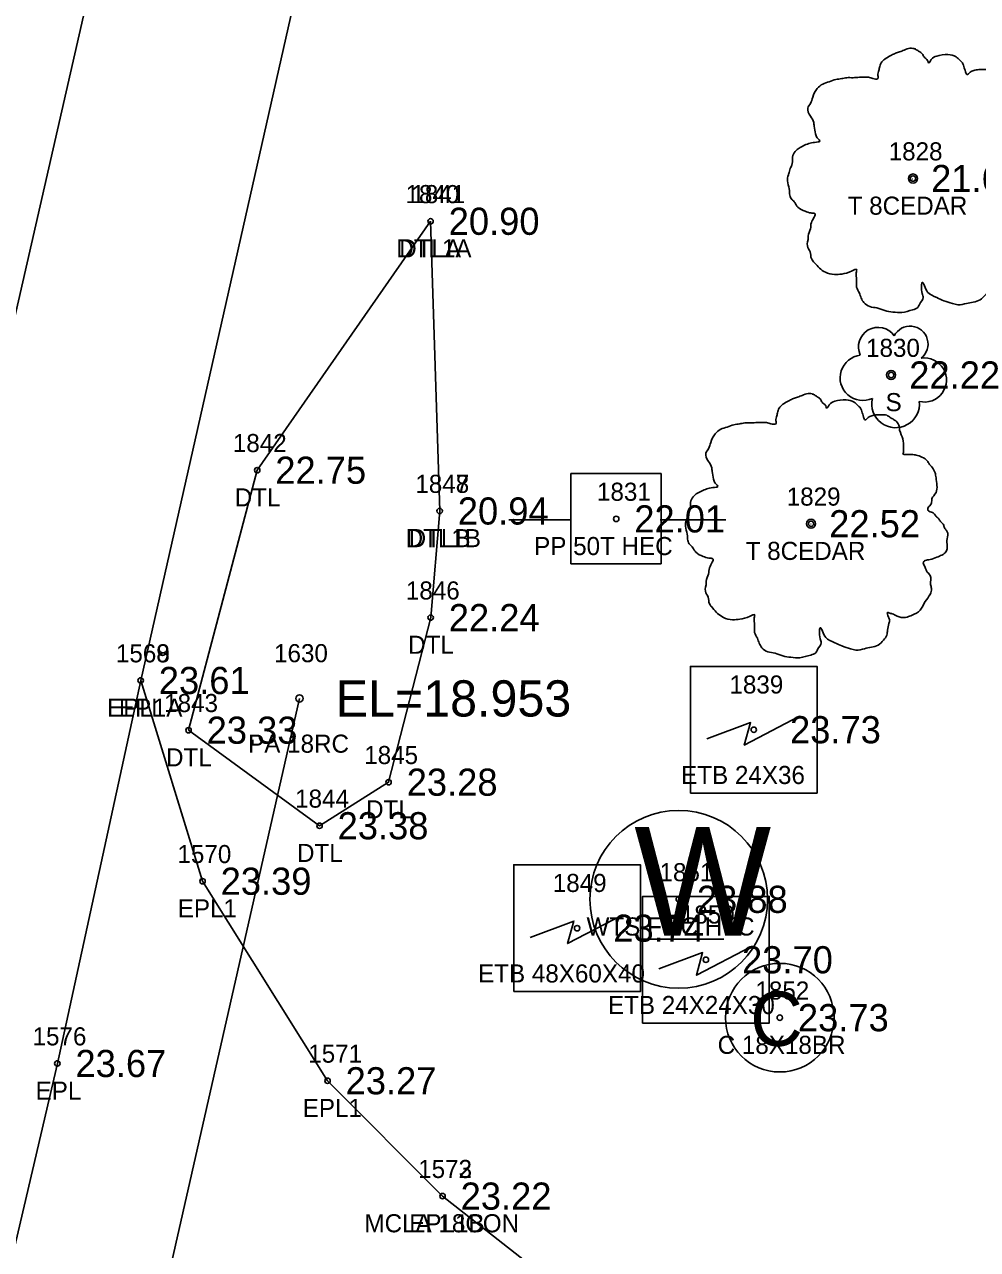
# Model space of a CAD drawing. Extents: x 2654414 to 2656963, y 761776 to 764965.
# Drawn here: x 2655624.8 to 2655677.5, y 762792.6 to 762860.3 of the extents above; entities that cross this region are included whole.
import ezdxf

# ---------------------------------------------------------------- set-up
doc = ezdxf.new("R2010")
doc.units = 0
for name, color, linetype in [('Default', 7, 'Continuous'), ('RD_EX_BldgApp', 7, 'Continuous'), ('RD_EX_BldgApp_txCode', 7, 'Continuous'), ('RD_EX_Conc', 7, 'Continuous'), ('RD_EX_Conc_txCode', 7, 'Continuous'), ('RD_EX_DR_Pipe', 7, 'Continuous'), ('RD_EX_DR_Pipe_txCode', 7, 'Continuous'), ('RD_EX_H2O', 7, 'Continuous'), ('RD_EX_H2O_txCode', 7, 'Continuous'), ('RD_EX_Road', 7, 'Continuous'), ('RD_EX_Road_txCode', 7, 'Continuous'), ('RD_EX_TX_BldgApp_ELEV', 7, 'Continuous'), ('RD_EX_TX_Conc_ELEV', 7, 'Continuous'), ('RD_EX_TX_H2O_ELEV', 7, 'Continuous'), ('RD_EX_TX_Road_ELEV', 7, 'Continuous'), ('RD_EX_TX_UT_ELEV', 7, 'Continuous'), ('RD_EX_TX_VEG_ELEV', 7, 'Continuous'), ('RD_EX_UT', 7, 'Continuous'), ('RD_EX_UT_txCode', 7, 'Continuous'), ('RD_EX_VEG', 7, 'Continuous'), ('RD_EX_VEG_txCode', 7, 'Continuous'), ('RD_HC_Cl', 7, 'Continuous'), ('RD_HC_Survey_ELEV', 7, 'Continuous'), ('RD_SMD_Locator', 7, 'Continuous'), ('RD_TX_Pipe_ElevEX', 7, 'Continuous')]:
    doc.layers.add(name, color=color, linetype=linetype)

msp = doc.modelspace()

# ---------------------------------------------------------------- linework, layer by layer
at = {"layer": 'Default'}
msp.add_line((2656050.51, 764712.367), (2655383.263, 761787.511), dxfattribs=at)
at = {"layer": 'RD_EX_BldgApp'}
msp.add_circle((2655666.585, 762805.403), 3, dxfattribs=at)
at = {"layer": 'RD_EX_Conc'}
msp.add_lwpolyline([(2655647.949, 762795.546), (2655656.497, 762788.848), (2655668.299, 762784.324), (2655695.432, 762778.051), (2655712.437, 762774.144), (2655737.025, 762767.62), (2655754.836, 762760.944), (2655757.409, 762759.817), (2655785.931, 762744.562)], dxfattribs=at)
at = {"layer": 'RD_EX_DR_Pipe'}
msp.add_line((2655640.047, 762823.04), (2655619.306, 762731.781), dxfattribs=at)
at = {"layer": 'RD_EX_H2O'}
msp.add_line((2655647.288, 762849.401), (2655647.792, 762833.395), dxfattribs=at)
msp.add_lwpolyline([(2655647.288, 762849.401), (2655637.708, 762835.648), (2655633.913, 762821.285), (2655641.15, 762816.006), (2655644.968, 762818.413), (2655647.293, 762827.505), (2655647.792, 762833.395)], dxfattribs=at)
at = {"layer": 'RD_EX_Road'}
for points in [[(2655670.037, 762995.178), (2655648.569, 762900.673), (2655631.27, 762824.032), (2655626.665, 762802.872), (2655621.781, 762781.907), (2655611.705, 762738.435), (2655604.931, 762708.622), (2655582.644, 762610.543), (2655576.456, 762583.319), (2655561.406, 762517.242), (2655539.154, 762414.805), (2655531.984, 762386.147), (2655517.984, 762324.295), (2655508.173, 762280.146), (2655501.462, 762251.601), (2655496.922, 762232.086), (2655477.204, 762144.974), (2655472.137, 762122.524), (2655453.741, 762045.099), (2655431.791, 761949.924), (2655409.76, 761853.25), (2655401.248, 761816.416), (2655394.612, 761787.366)], [(2655631.27, 762824.032), (2655634.687, 762812.942), (2655641.592, 762801.917), (2655647.949, 762795.546)]]:
    msp.add_lwpolyline(points, dxfattribs=at)
at = {"layer": 'RD_EX_UT'}
for p, q in [((2655660.036, 762835.467), (2655655.036, 762835.467)), ((2655655.036, 762835.467), (2655655.036, 762830.467)), ((2655660.036, 762830.467), (2655660.036, 762835.467)), ((2655651.605, 762832.905), (2655655.074, 762832.905)), ((2655659.965, 762832.905), (2655663.605, 762832.905)), ((2655655.036, 762830.467), (2655660.036, 762830.467)), ((2655658.872, 762809.734), (2655663.501, 762809.734))]:
    msp.add_line(p, q, dxfattribs=at)
for points in [[(2655661.649, 762817.811), (2655661.649, 762824.811), (2655668.649, 762824.811), (2655668.649, 762817.811)], [(2655651.886, 762806.847), (2655651.886, 762813.847), (2655658.886, 762813.847), (2655658.886, 762806.847)], [(2655658.999, 762805.103), (2655658.999, 762812.103), (2655665.999, 762812.103), (2655665.999, 762805.103)]]:
    msp.add_lwpolyline(points, close=True, dxfattribs=at)
for points in [[(2655662.547, 762820.805), (2655664.969, 762821.705), (2655664.623, 762820.459), (2655667.668, 762822.052)], [(2655652.784, 762809.841), (2655655.207, 762810.741), (2655654.861, 762809.495), (2655657.906, 762811.088)], [(2655659.898, 762808.097), (2655662.32, 762808.998), (2655661.974, 762807.751), (2655665.019, 762809.344)]]:
    msp.add_lwpolyline(points, dxfattribs=at)
msp.add_circle((2655661, 762811.942), 4.908, dxfattribs=at)
at = {"layer": 'RD_EX_VEG'}
for centre, radius in [((2655673.947, 762851.763), 0.25), ((2655673.934, 762851.744), 0.0001), ((2655672.737, 762840.909), 0.25), ((2655668.312, 762832.691), 0.25), ((2655668.3, 762832.672), 0.0001)]:
    msp.add_circle(centre, radius, dxfattribs=at)
for centre, radius, start, end in [((2655672.016, 762842.457), 1.084, 34.97629, 204.75602), ((2655673.782, 762842.611), 0.995, 308.76261, 152.04674), ((2655671.173, 762840.754), 1.257, 96.45179, 294.73401), ((2655674.577, 762840.63), 1.218, 256.56668, 98.10463), ((2655672.983, 762839.313), 1.318, 166.88266, 5.75893)]:
    msp.add_arc(centre, radius, start, end, dxfattribs=at)
for points in [[(2655674.079, 762858.93), (2655673.779, 762858.955), (2655673.454, 762858.855), (2655673.204, 762858.755), (2655672.979, 762858.68), (2655672.755, 762858.58), (2655672.455, 762858.406), (2655672.23, 762858.206), (2655672.105, 762857.956), (2655672.055, 762857.731), (2655672.005, 762857.456), (2655672.005, 762857.281), (2655671.88, 762857.256), (2655671.73, 762857.281), (2655671.48, 762857.356), (2655671.23, 762857.356), (2655670.98, 762857.356), (2655670.63, 762857.331), (2655670.281, 762857.331), (2655670.006, 762857.281), (2655669.681, 762857.231), (2655669.306, 762857.106), (2655668.956, 762856.981), (2655668.656, 762856.731), (2655668.406, 762856.256), (2655668.281, 762855.907), (2655668.132, 762855.657), (2655668.281, 762855.207), (2655668.456, 762854.857), (2655668.481, 762854.657), (2655668.556, 762854.232), (2655668.656, 762854.007), (2655668.781, 762853.807), (2655668.706, 762853.783), (2655668.331, 762853.733), (2655668.032, 762853.633), (2655667.607, 762853.408), (2655667.382, 762853.183), (2655667.282, 762852.858), (2655667.257, 762852.508), (2655667.157, 762852.308), (2655667.082, 762852.033), (2655667.057, 762851.958), (2655667.007, 762851.633), (2655667.107, 762851.184), (2655667.132, 762850.834), (2655667.257, 762850.609), (2655667.407, 762850.434), (2655667.582, 762850.184), (2655667.982, 762849.959), (2655668.306, 762849.859), (2655668.506, 762849.834), (2655668.331, 762849.334), (2655668.281, 762848.985), (2655668.157, 762848.585), (2655668.157, 762848.51), (2655668.107, 762848.035), (2655668.256, 762847.71), (2655668.331, 762847.335), (2655668.506, 762847.11), (2655668.781, 762846.811), (2655669.106, 762846.586), (2655669.606, 762846.461), (2655670.006, 762846.486), (2655670.581, 762846.661), (2655670.83, 762846.736), (2655670.805, 762846.561), (2655670.83, 762846.186), (2655670.83, 762845.761), (2655670.98, 762845.436), (2655671.08, 762845.161), (2655671.23, 762844.911), (2655671.555, 762844.687), (2655671.955, 762844.612), (2655672.38, 762844.462), (2655672.83, 762844.387), (2655673.329, 762844.362), (2655673.929, 762844.512), (2655674.204, 762844.637), (2655674.304, 762844.811), (2655674.504, 762845.186), (2655674.454, 762845.411), (2655674.479, 762846.011), (2655674.579, 762845.836), (2655674.754, 762845.486), (2655675.253, 762845.186), (2655675.653, 762845.011), (2655676.128, 762844.861), (2655676.428, 762844.786), (2655676.903, 762844.861), (2655677.278, 762844.936), (2655677.652, 762845.061), (2655677.952, 762845.336), (2655678.127, 762845.611), (2655678.177, 762845.886), (2655678.252, 762846.261), (2655678.302, 762846.436)], [(2655678.302, 762846.436), (2655678.227, 762846.611), (2655678.177, 762846.861), (2655678.252, 762846.836), (2655678.427, 762846.786), (2655678.702, 762846.661), (2655678.927, 762846.586), (2655679.252, 762846.611), (2655679.527, 762846.711), (2655679.976, 762846.986), (2655680.251, 762847.46), (2655680.526, 762847.86), (2655680.601, 762848.185), (2655680.551, 762848.41), (2655680.526, 762848.91), (2655680.326, 762849.16), (2655680.276, 762849.284), (2655680.176, 762849.684), (2655680.251, 762849.734), (2655680.526, 762849.784), (2655680.901, 762849.909), (2655681.176, 762850.034), (2655681.401, 762850.209), (2655681.476, 762850.434), (2655681.451, 762850.834), (2655681.501, 762851.234), (2655681.426, 762851.384), (2655681.326, 762851.533), (2655681.251, 762851.733), (2655681.101, 762851.883), (2655681.001, 762852.033), (2655680.901, 762852.133), (2655680.776, 762852.283), (2655680.601, 762852.408), (2655680.451, 762852.458), (2655680.401, 762852.608), (2655680.551, 762852.808), (2655680.601, 762852.908), (2655680.626, 762853.133), (2655680.851, 762853.483), (2655680.901, 762853.882), (2655680.851, 762854.307), (2655680.801, 762854.582), (2655680.651, 762854.857), (2655680.451, 762855.107), (2655680.326, 762855.282), (2655680.151, 762855.407), (2655679.826, 762855.532), (2655679.577, 762855.582), (2655679.227, 762855.582), (2655679.027, 762855.632), (2655679.052, 762855.682), (2655679.052, 762855.832), (2655679.052, 762856.107), (2655678.977, 762856.556), (2655678.827, 762857.056), (2655678.827, 762857.081), (2655678.727, 762857.331), (2655678.502, 762857.531), (2655678.327, 762857.631), (2655678.127, 762857.756), (2655677.877, 762857.781), (2655677.577, 762857.781), (2655677.303, 762857.731), (2655677.103, 762857.631), (2655676.928, 762857.506), (2655676.853, 762857.656), (2655676.753, 762857.956), (2655676.703, 762858.106), (2655676.553, 762858.281), (2655676.328, 762858.48), (2655675.878, 762858.605), (2655675.253, 762858.53), (2655674.954, 762858.331), (2655674.804, 762858.156), (2655674.754, 762858.281), (2655674.554, 762858.48), (2655674.454, 762858.655), (2655674.279, 762858.78), (2655674.129, 762858.88), (2655674.029, 762858.93)], [(2655668.444, 762839.858), (2655668.144, 762839.883), (2655667.819, 762839.783), (2655667.569, 762839.683), (2655667.345, 762839.608), (2655667.12, 762839.508), (2655666.82, 762839.333), (2655666.595, 762839.133), (2655666.47, 762838.883), (2655666.42, 762838.658), (2655666.37, 762838.383), (2655666.37, 762838.208), (2655666.245, 762838.183), (2655666.095, 762838.208), (2655665.845, 762838.283), (2655665.595, 762838.283), (2655665.345, 762838.283), (2655664.996, 762838.258), (2655664.646, 762838.258), (2655664.371, 762838.208), (2655664.046, 762838.159), (2655663.671, 762838.034), (2655663.321, 762837.909), (2655663.021, 762837.659), (2655662.772, 762837.184), (2655662.647, 762836.834), (2655662.497, 762836.584), (2655662.647, 762836.134), (2655662.822, 762835.785), (2655662.846, 762835.585), (2655662.921, 762835.16), (2655663.021, 762834.935), (2655663.146, 762834.735), (2655663.071, 762834.71), (2655662.697, 762834.66), (2655662.397, 762834.56), (2655661.972, 762834.335), (2655661.747, 762834.11), (2655661.647, 762833.785), (2655661.622, 762833.436), (2655661.522, 762833.236), (2655661.447, 762832.961), (2655661.422, 762832.886), (2655661.372, 762832.561), (2655661.472, 762832.111), (2655661.497, 762831.761), (2655661.622, 762831.536), (2655661.772, 762831.362), (2655661.947, 762831.112), (2655662.347, 762830.887), (2655662.672, 762830.787), (2655662.871, 762830.762), (2655662.697, 762830.262), (2655662.647, 762829.912), (2655662.522, 762829.512), (2655662.522, 762829.437), (2655662.472, 762828.963), (2655662.622, 762828.638), (2655662.697, 762828.263), (2655662.871, 762828.038), (2655663.146, 762827.738), (2655663.471, 762827.513), (2655663.971, 762827.388), (2655664.371, 762827.413), (2655664.946, 762827.588), (2655665.195, 762827.663), (2655665.17, 762827.488), (2655665.195, 762827.113), (2655665.195, 762826.689), (2655665.345, 762826.364), (2655665.445, 762826.089), (2655665.595, 762825.839), (2655665.92, 762825.614), (2655666.32, 762825.539), (2655666.745, 762825.389), (2655667.195, 762825.314), (2655667.694, 762825.289), (2655668.294, 762825.439), (2655668.569, 762825.564), (2655668.669, 762825.739), (2655668.869, 762826.114), (2655668.819, 762826.339), (2655668.844, 762826.938), (2655668.944, 762826.763), (2655669.119, 762826.414), (2655669.619, 762826.114), (2655670.018, 762825.939), (2655670.493, 762825.789), (2655670.793, 762825.714), (2655671.268, 762825.789), (2655671.643, 762825.864), (2655672.017, 762825.989), (2655672.317, 762826.264), (2655672.492, 762826.539), (2655672.542, 762826.813), (2655672.617, 762827.188), (2655672.667, 762827.363)], [(2655672.667, 762827.363), (2655672.592, 762827.538), (2655672.542, 762827.788), (2655672.617, 762827.763), (2655672.792, 762827.713), (2655673.067, 762827.588), (2655673.292, 762827.513), (2655673.617, 762827.538), (2655673.892, 762827.638), (2655674.341, 762827.913), (2655674.616, 762828.388), (2655674.891, 762828.788), (2655674.966, 762829.112), (2655674.916, 762829.337), (2655674.891, 762829.837), (2655674.691, 762830.087), (2655674.641, 762830.212), (2655674.541, 762830.612), (2655674.616, 762830.662), (2655674.891, 762830.712), (2655675.266, 762830.837), (2655675.541, 762830.962), (2655675.766, 762831.137), (2655675.841, 762831.362), (2655675.816, 762831.761), (2655675.866, 762832.161), (2655675.791, 762832.311), (2655675.691, 762832.461), (2655675.616, 762832.661), (2655675.466, 762832.811), (2655675.366, 762832.961), (2655675.266, 762833.061), (2655675.141, 762833.211), (2655674.966, 762833.336), (2655674.816, 762833.386), (2655674.766, 762833.536), (2655674.916, 762833.735), (2655674.966, 762833.835), (2655674.991, 762834.06), (2655675.216, 762834.41), (2655675.266, 762834.81), (2655675.216, 762835.235), (2655675.166, 762835.51), (2655675.016, 762835.785), (2655674.816, 762836.034), (2655674.691, 762836.209), (2655674.516, 762836.334), (2655674.192, 762836.459), (2655673.942, 762836.509), (2655673.592, 762836.509), (2655673.392, 762836.559), (2655673.417, 762836.609), (2655673.417, 762836.759), (2655673.417, 762837.034), (2655673.342, 762837.484), (2655673.192, 762837.984), (2655673.192, 762838.009), (2655673.092, 762838.258), (2655672.867, 762838.458), (2655672.692, 762838.558), (2655672.492, 762838.683), (2655672.242, 762838.708), (2655671.943, 762838.708), (2655671.668, 762838.658), (2655671.468, 762838.558), (2655671.293, 762838.433), (2655671.218, 762838.583), (2655671.118, 762838.883), (2655671.068, 762839.033), (2655670.918, 762839.208), (2655670.693, 762839.408), (2655670.243, 762839.533), (2655669.619, 762839.458), (2655669.319, 762839.258), (2655669.169, 762839.083), (2655669.119, 762839.208), (2655668.919, 762839.408), (2655668.819, 762839.583), (2655668.644, 762839.708), (2655668.494, 762839.808), (2655668.394, 762839.858)]]:
    msp.add_spline(points, degree=3, dxfattribs=at)
at = {"layer": 'RD_HC_Cl'}
msp.add_line((2656050.51, 764712.367), (2655383.263, 761787.511), dxfattribs=at)
at = {"layer": 'RD_SMD_Locator'}
for centre, radius in [((2655673.947, 762851.763), 0.15), ((2655647.288, 762849.401), 0.15), ((2655647.288, 762849.401), 0.15), ((2655672.737, 762840.909), 0.15), ((2655637.708, 762835.648), 0.15), ((2655647.792, 762833.395), 0.15), ((2655647.792, 762833.395), 0.15), ((2655657.545, 762832.958), 0.15), ((2655668.312, 762832.691), 0.15), ((2655647.293, 762827.505), 0.15), ((2655631.27, 762824.032), 0.15), ((2655631.27, 762824.032), 0.15), ((2655640.047, 762823.04), 0.2), ((2655633.913, 762821.285), 0.15), ((2655665.149, 762821.311), 0.15), ((2655644.968, 762818.413), 0.15), ((2655641.15, 762816.006), 0.15), ((2655634.687, 762812.942), 0.15), ((2655661.001, 762811.942), 0.15), ((2655655.386, 762810.347), 0.15), ((2655662.499, 762808.603), 0.15), ((2655666.585, 762805.403), 0.15), ((2655626.665, 762802.872), 0.15), ((2655641.592, 762801.917), 0.15), ((2655647.949, 762795.546), 0.15), ((2655647.949, 762795.546), 0.15)]:
    msp.add_circle(centre, radius, dxfattribs=at)

# ---------------------------------------------------------------- texts
at = {"layer": 'RD_EX_BldgApp'}
msp.add_text('C', height=3, dxfattribs=at).set_placement((2655664.955, 762803.842))
at = {"layer": 'RD_EX_BldgApp_txCode'}
for s, p in [('1852', (2655665.239, 762806.403)), ('C 18X18BR', (2655663.152, 762803.403))]:
    msp.add_text(s, height=1, dxfattribs=at).set_placement(p)
at = {"layer": 'RD_EX_Conc_txCode'}
for s, p in [('1573', (2655646.603, 762796.546)), ('MCLA 18CON', (2655643.634, 762793.546))]:
    msp.add_text(s, height=1, dxfattribs=at).set_placement(p)
at = {"layer": 'RD_EX_DR_Pipe_txCode'}
for s, p in [('1630', (2655638.638, 762825.04)), ('PA 18RC', (2655637.205, 762820.04))]:
    msp.add_text(s, height=1, dxfattribs=at).set_placement(p)
at = {"layer": 'RD_EX_H2O_txCode'}
for s, p in [('1840', (2655645.902, 762850.401)), ('1841', (2655646.225, 762850.401)), ('DTL1A', (2655645.39, 762847.401)), ('DTLA', (2655645.555, 762847.401)), ('1842', (2655636.362, 762836.648)), ('1847', (2655646.446, 762834.395)), ('1848', (2655646.446, 762834.395)), ('DTL', (2655636.464, 762833.648)), ('DTL1B', (2655645.91, 762831.395)), ('DTLB', (2655646.076, 762831.395)), ('1846', (2655645.923, 762828.505)), ('DTL', (2655646.049, 762825.505)), ('1843', (2655632.566, 762822.285)), ('DTL', (2655632.669, 762819.285)), ('1845', (2655643.621, 762819.413)), ('1844', (2655639.803, 762817.006)), ('DTL', (2655643.724, 762816.413)), ('DTL', (2655639.906, 762814.006))]:
    msp.add_text(s, height=1, dxfattribs=at).set_placement(p)
at = {"layer": 'RD_EX_Road_txCode'}
for s, p in [('1568', (2655629.9, 762825.032)), ('1569', (2655629.9, 762825.032)), ('EPL1A', (2655629.412, 762822.032)), ('EPL', (2655630.065, 762822.032)), ('1570', (2655633.301, 762813.942)), ('EPL1', (2655633.317, 762810.942)), ('1576', (2655625.295, 762803.872)), ('1571', (2655640.529, 762802.917)), ('EPL', (2655625.46, 762800.872)), ('EPL1', (2655640.222, 762799.917)), ('1572', (2655646.603, 762796.546)), ('EPL1B', (2655646.107, 762793.546))]:
    msp.add_text(s, height=1, dxfattribs=at).set_placement(p)
at = {"layer": 'RD_EX_TX_BldgApp_ELEV'}
msp.add_text('23.73', height=1.5, dxfattribs=at).set_placement((2655667.585, 762804.653))
at = {"layer": 'RD_EX_TX_Conc_ELEV'}
msp.add_text('23.22', height=1.5, dxfattribs=at).set_placement((2655648.949, 762794.796))
at = {"layer": 'RD_EX_TX_H2O_ELEV'}
for s, p in [('20.90', (2655648.288, 762848.651)), ('20.90', (2655648.288, 762848.651)), ('22.75', (2655638.708, 762834.898)), ('20.94', (2655648.792, 762832.645)), ('20.94', (2655648.792, 762832.645)), ('22.24', (2655648.293, 762826.755)), ('23.33', (2655634.913, 762820.535)), ('23.28', (2655645.968, 762817.663)), ('23.38', (2655642.15, 762815.256))]:
    msp.add_text(s, height=1.5, dxfattribs=at).set_placement(p)
at = {"layer": 'RD_EX_TX_Road_ELEV'}
for s, p in [('23.61', (2655632.27, 762823.282)), ('23.61', (2655632.27, 762823.282)), ('23.39', (2655635.687, 762812.192)), ('23.67', (2655627.665, 762802.122)), ('23.27', (2655642.592, 762801.167)), ('23.22', (2655648.949, 762794.796))]:
    msp.add_text(s, height=1.5, dxfattribs=at).set_placement(p)
at = {"layer": 'RD_EX_TX_UT_ELEV'}
for s, p in [('23.73', (2655667.149, 762820.561)), ('23.88', (2655662.001, 762811.192)), ('23.74', (2655657.386, 762809.597)), ('23.70', (2655664.499, 762807.853))]:
    msp.add_text(s, height=1.5, dxfattribs=at).set_placement(p)
at = {"layer": 'RD_EX_TX_VEG_ELEV'}
for s, p in [('21.69', (2655674.947, 762851.013)), ('22.22', (2655673.737, 762840.159)), ('22.52', (2655669.312, 762831.941))]:
    msp.add_text(s, height=1.5, dxfattribs=at).set_placement(p)
at = {"layer": 'RD_EX_UT'}
msp.add_text('W', height=6, dxfattribs=at).set_placement((2655658.536, 762809.941))
at = {"layer": 'RD_EX_UT_txCode'}
for s, p in [('1831', (2655656.482, 762833.958)), ('PP 50T HEC', (2655653.01, 762830.958)), ('1839', (2655663.802, 762823.311)), ('ETB 24X36', (2655661.133, 762818.311)), ('1851', (2655659.938, 762812.942)), ('1849', (2655654.039, 762812.347)), ('1850', (2655661.114, 762810.603)), ('WTS FOC HTC', (2655655.906, 762809.942)), ('ETB 48X60X40', (2655649.913, 762807.347)), ('ETB 24X24X30', (2655657.09, 762805.603))]:
    msp.add_text(s, height=1, dxfattribs=at).set_placement(p)
at = {"layer": 'RD_EX_VEG_txCode'}
for s, p in [('1828', (2655672.601, 762852.763)), ('T 8CEDAR', (2655670.333, 762849.763)), ('1830', (2655671.351, 762841.909)), ('S', (2655672.43, 762838.909)), ('1829', (2655666.966, 762833.691)), ('T 8CEDAR', (2655664.698, 762830.691))]:
    msp.add_text(s, height=1, dxfattribs=at).set_placement(p)
at = {"layer": 'RD_HC_Survey_ELEV'}
msp.add_text('22.01', height=1.5, dxfattribs=at).set_placement((2655658.545, 762832.208))
at = {"layer": 'RD_TX_Pipe_ElevEX'}
msp.add_text('EL=18.953', height=2, dxfattribs=at).set_placement((2655642.047, 762822.04))

doc.saveas('drawing.dxf')
